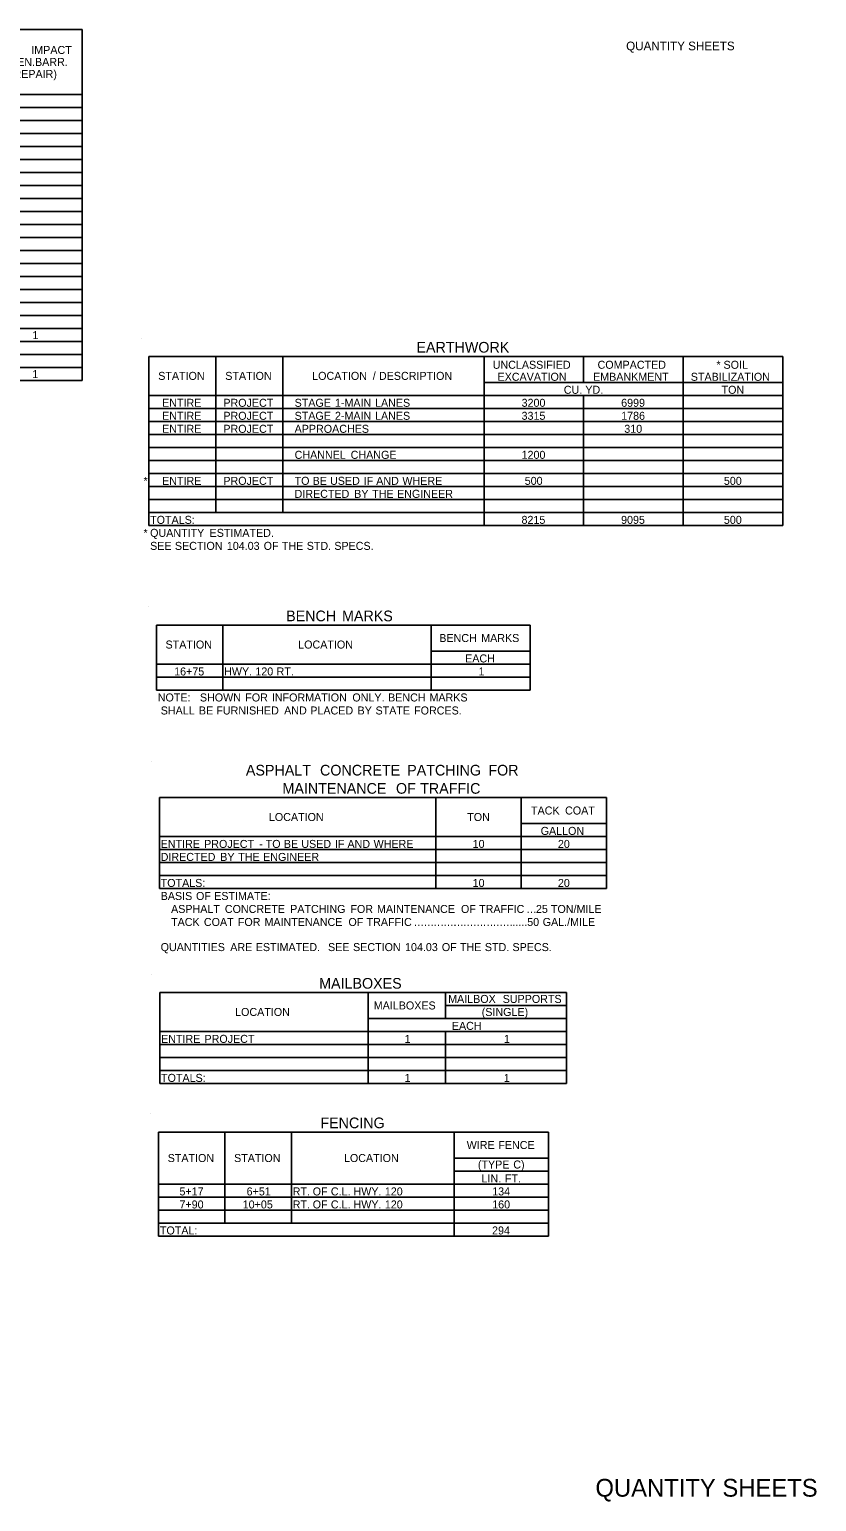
# Model space of a CAD drawing. Extents: x 1940653 to 1945779, y 534266 to 535271.
# Drawn here: x 1941662 to 1942192, y 534266 to 535259 of the extents above; entities that cross this region are included whole.
import ezdxf

# ---------------------------------------------------------------- set-up
doc = ezdxf.new("R2010")
doc.units = 0
for name, color, linetype in [('Default', 7, 'Continuous'), ('R_Border Prem', 7, 'Continuous'), ('R_Logo', 7, 'Continuous')]:
    doc.layers.add(name, color=color, linetype=linetype)

msp = doc.modelspace()

# ---------------------------------------------------------------- linework, layer by layer
at = {"layer": 'Default'}
for p, q in [((1940658.64, 535258.6), (1941697.16, 535258.6)), ((1941697.16, 535021.67), (1941697.16, 535258.6)), ((1941697.16, 535021.67), (1941697.16, 535258.6)), ((1941170.66, 535205.95), (1941697.16, 535205.95)), ((1941222.87, 535214.72), (1941697.16, 535214.72)), ((1941448.83, 535214.72), (1941697.16, 535214.72)), ((1940658.64, 535197.17), (1941697.16, 535197.17)), ((1940658.64, 535188.4), (1941697.16, 535188.4)), ((1940658.64, 535179.62), (1941697.16, 535179.62)), ((1940658.64, 535170.85), (1941697.16, 535170.85)), ((1940658.64, 535162.07), (1941697.16, 535162.07)), ((1940658.64, 535153.3), (1941697.16, 535153.3)), ((1940658.64, 535144.52), (1941697.16, 535144.52)), ((1940658.64, 535135.75), (1941697.16, 535135.75)), ((1940658.64, 535126.97), (1941697.16, 535126.97)), ((1940658.64, 535118.2), (1941697.16, 535118.2)), ((1940658.64, 535109.42), (1941697.16, 535109.42)), ((1940658.64, 535100.65), (1941697.16, 535100.65)), ((1940658.64, 535091.87), (1941697.16, 535091.87)), ((1940658.64, 535083.1), (1941697.16, 535083.1)), ((1940658.64, 535074.32), (1941697.16, 535074.32)), ((1940658.64, 535065.55), (1941697.16, 535065.55)), ((1940658.64, 535056.77), (1941697.16, 535056.77)), ((1940658.64, 535048), (1941697.16, 535048)), ((1940658.64, 535039.22), (1941697.16, 535039.22)), ((1941741.99, 535038.05), (1942169.33, 535038.05)), ((1941741.99, 534923.98), (1941741.99, 535038.05)), ((1941741.99, 534923.98), (1941741.99, 535038.05)), ((1941787.18, 534932.75), (1941787.18, 535038.05)), ((1941832.37, 534932.75), (1941832.37, 535038.05)), ((1941967.95, 534923.98), (1941967.95, 535038.05)), ((1942035.08, 535020.5), (1942035.08, 535038.05)), ((1942102.2, 534923.98), (1942102.2, 535038.05)), ((1942169.33, 534923.98), (1942169.33, 535038.05)), ((1942169.33, 534923.98), (1942169.33, 535038.05)), ((1940658.64, 535030.45), (1941697.16, 535030.45)), ((1940658.64, 535021.67), (1941697.16, 535021.67)), ((1941967.95, 535020.5), (1942169.33, 535020.5)), ((1941741.99, 535011.73), (1942169.33, 535011.73)), ((1941787.18, 534932.75), (1941787.18, 535011.73)), ((1941832.37, 534932.75), (1941832.37, 535011.73)), ((1941967.95, 534932.75), (1941967.95, 535011.73)), ((1942035.08, 534923.98), (1942035.08, 535011.73)), ((1942035.08, 534932.75), (1942035.08, 535011.73)), ((1942102.2, 534932.75), (1942102.2, 535011.73)), ((1941741.99, 535002.95), (1942169.33, 535002.95)), ((1941741.99, 534994.18), (1942169.33, 534994.18)), ((1941741.99, 534985.4), (1942169.33, 534985.4)), ((1941741.99, 534976.63), (1942169.33, 534976.63)), ((1941741.99, 534967.85), (1942169.33, 534967.85)), ((1941741.99, 534959.08), (1942169.33, 534959.08)), ((1941741.99, 534950.3), (1942169.33, 534950.3)), ((1941741.99, 534941.53), (1942169.33, 534941.53)), ((1941741.99, 534932.75), (1941787.18, 534932.75)), ((1941741.99, 534932.75), (1942169.33, 534932.75)), ((1942035.08, 534932.75), (1942102.2, 534932.75)), ((1942102.2, 534932.75), (1942169.33, 534932.75)), ((1941741.99, 534923.98), (1942169.33, 534923.98)), ((1941747.14, 534856.82), (1941998.98, 534856.82)), ((1941747.14, 534812.94), (1941747.14, 534856.82)), ((1941747.14, 534812.94), (1941747.14, 534856.82)), ((1941791.89, 534812.94), (1941791.89, 534856.82)), ((1941932.29, 534812.94), (1941932.29, 534856.82)), ((1941998.98, 534812.94), (1941998.98, 534856.82)), ((1941932.29, 534839.27), (1941998.98, 534839.27)), ((1941998.98, 534812.94), (1941998.98, 534839.27)), ((1941747.14, 534830.49), (1941998.98, 534830.49)), ((1941932.29, 534812.94), (1941932.29, 534830.49)), ((1941747.14, 534821.72), (1941998.98, 534821.72)), ((1941747.14, 534812.94), (1941998.98, 534812.94)), ((1941749.11, 534740.46), (1942050.53, 534740.46)), ((1941749.11, 534679.04), (1941749.11, 534740.46)), ((1941749.11, 534679.04), (1941749.11, 534740.46)), ((1941935.57, 534679.04), (1941935.57, 534740.46)), ((1941993.05, 534679.04), (1941993.05, 534740.46)), ((1942050.53, 534679.04), (1942050.53, 534740.46)), ((1942050.53, 534722.91), (1942050.53, 534740.46)), ((1941993.05, 534722.91), (1942050.53, 534722.91)), ((1941993.05, 534679.04), (1941993.05, 534722.91)), ((1941749.11, 534714.14), (1942050.53, 534714.14)), ((1941935.57, 534679.04), (1941935.57, 534714.14)), ((1942050.53, 534696.59), (1942050.53, 534714.14)), ((1941749.11, 534705.36), (1942050.53, 534705.36)), ((1941749.11, 534696.59), (1942050.53, 534696.59)), ((1941749.11, 534687.81), (1942050.53, 534687.81)), ((1941749.11, 534679.04), (1942050.53, 534679.04)), ((1942050.53, 534679.04), (1942050.53, 534687.81)), ((1941749.37, 534608.95), (1942023.58, 534608.95)), ((1941749.37, 534547.53), (1941749.37, 534608.95)), ((1941749.37, 534547.53), (1941749.37, 534608.95)), ((1941889.77, 534547.53), (1941889.77, 534608.95)), ((1941941.98, 534591.4), (1941941.98, 534608.95)), ((1941941.98, 534600.18), (1942023.58, 534600.18)), ((1942023.58, 534600.18), (1942023.58, 534608.95)), ((1942023.58, 534547.53), (1942023.58, 534608.95)), ((1941889.77, 534591.4), (1942023.58, 534591.4)), ((1941941.98, 534591.4), (1942023.58, 534591.4)), ((1942023.58, 534547.53), (1942023.58, 534591.4)), ((1941749.37, 534582.63), (1942023.58, 534582.63)), ((1941889.77, 534547.53), (1941889.77, 534582.63)), ((1941941.98, 534547.53), (1941941.98, 534582.63)), ((1941941.98, 534547.53), (1941941.98, 534582.63)), ((1941749.37, 534573.85), (1942023.58, 534573.85)), ((1941749.37, 534565.08), (1942023.58, 534565.08)), ((1941749.37, 534556.3), (1942023.58, 534556.3)), ((1941749.37, 534547.53), (1942023.58, 534547.53)), ((1941748.59, 534514.81), (1942011.4, 534514.81)), ((1941748.59, 534444.61), (1941748.59, 534514.81)), ((1941748.59, 534444.61), (1941748.59, 534514.81)), ((1941793.34, 534453.39), (1941793.34, 534514.81)), ((1941838.1, 534453.39), (1941838.1, 534514.81)), ((1941947.78, 534444.61), (1941947.78, 534514.81)), ((1942011.4, 534497.26), (1942011.4, 534514.81)), ((1942011.4, 534444.61), (1942011.4, 534514.81)), ((1941947.78, 534497.26), (1942011.4, 534497.26)), ((1941947.78, 534488.49), (1942011.4, 534488.49)), ((1941947.78, 534488.49), (1942011.4, 534488.49)), ((1942011.4, 534444.61), (1942011.4, 534488.49)), ((1941748.59, 534479.71), (1942011.4, 534479.71)), ((1941748.59, 534470.94), (1942011.4, 534470.94)), ((1941793.34, 534453.39), (1941793.34, 534479.71)), ((1941838.1, 534453.39), (1941838.1, 534479.71)), ((1941947.78, 534444.61), (1941947.78, 534479.71)), ((1941748.59, 534462.16), (1942011.4, 534462.16)), ((1941748.59, 534453.39), (1942011.4, 534453.39)), ((1941748.59, 534444.61), (1942011.4, 534444.61))]:
    msp.add_line(p, q, dxfattribs=at)
at = {"layer": 'R_Logo'}
for p, q in [((1941736.73, 535050.34), (1941736.73, 535050.34)), ((1941741.87, 534869.1), (1941741.87, 534869.1)), ((1941743.84, 534765.03), (1941743.84, 534765.03)), ((1941744.1, 534621.24), (1941744.1, 534621.24)), ((1941743.33, 534527.1), (1941743.33, 534527.1))]:
    msp.add_line(p, q, dxfattribs=at)

# ---------------------------------------------------------------- texts
at = {"layer": 'Default'}
for s, height, p in [(' IMPACT', 5.4, (1941660.75, 535242.06)), ('ATTEN.BARR.', 5.4, (1941639.6, 535233.96)), ('(REPAIR)', 5.4, (1941648.34, 535225.86)), ('1', 5.4, (1941663.51, 535049.68)), ('EARTHWORK', 7.2, (1941922.42, 535040.59)), ('1', 5.4, (1941663.43, 535023.36)), ('STATION', 5.4, (1941748.33, 535022.19)), ('STATION', 5.4, (1941793.52, 535022.19)), ('LOCATION', 5.4, (1941852.13, 535022.19)), (' /', 5.4, (1941890.93, 535022.19)), (' DESCRIPTION', 5.4, (1941895.13, 535022.19)), ('UNCLASSIFIED', 5.4, (1941973.82, 535029.68)), ('EXCAVATION', 5.4, (1941977.08, 535021.58)), ('EMBANKMENT', 5.4, (1942041.47, 535021.58)), ('COMPACTED', 5.4, (1942044.51, 535029.68)), ('STABILIZATION', 5.4, (1942107.36, 535021.58)), ('*', 5.4, (1942124.64, 535029.68)), (' SOIL', 5.4, (1942127.42, 535029.68)), ('CU.', 5.4, (1942021.76, 535012.81)), (' YD.', 5.4, (1942034.24, 535012.81)), ('TON', 5.4, (1942128.11, 535012.81)), ('ENTIRE', 5.4, (1941750.95, 535004.03)), ('PROJECT', 5.4, (1941792.24, 535004.03)), ('STAGE', 5.4, (1941840.27, 535004.03)), (' 1-MAIN', 5.4, (1941865.45, 535004.03)), (' LANES', 5.4, (1941892.49, 535004.03)), ('3200', 5.4, (1941993.3, 535004.03)), ('6999', 5.4, (1942060.42, 535004.03)), ('ENTIRE', 5.4, (1941750.95, 534995.26)), ('PROJECT', 5.4, (1941792.24, 534995.26)), ('STAGE', 5.4, (1941840.27, 534995.26)), (' 2-MAIN', 5.4, (1941865.45, 534995.26)), (' LANES', 5.4, (1941892.49, 534995.26)), ('3315', 5.4, (1941993.27, 534995.26)), ('1786', 5.4, (1942060.42, 534995.26)), ('ENTIRE', 5.4, (1941750.95, 534986.48)), ('PROJECT', 5.4, (1941792.24, 534986.48)), ('APPROACHES', 5.4, (1941840.27, 534986.48)), ('310', 5.4, (1942062.53, 534986.48)), ('CHANNEL', 5.4, (1941840.27, 534968.93)), (' CHANGE', 5.4, (1941876.06, 534968.93)), ('1200', 5.4, (1941993.3, 534968.93)), ('*', 5.4, (1941738.44, 534951.38)), ('ENTIRE', 5.4, (1941750.95, 534951.38)), ('PROJECT', 5.4, (1941792.24, 534951.38)), ('TO', 5.4, (1941840.27, 534951.38)), ('DIRECTED', 5.4, (1941840.27, 534942.61)), (' BE', 5.4, (1941850.41, 534951.38)), (' USED', 5.4, (1941862.17, 534951.38)), (' BY', 5.4, (1941878.44, 534942.61)), (' IF', 5.4, (1941884.83, 534951.38)), (' THE', 5.4, (1941890.54, 534942.61)), (' AND', 5.4, (1941893.28, 534951.38)), (' ENGINEER', 5.4, (1941907.33, 534942.61)), (' WHERE', 5.4, (1941910.91, 534951.38)), ('500', 5.4, (1941995.4, 534951.38)), ('500', 5.4, (1942129.66, 534951.38)), ('TOTALS:', 5.4, (1941742.87, 534925.06)), ('8215', 5.4, (1941993.24, 534925.06)), ('9095', 5.4, (1942060.37, 534925.06)), ('500', 5.4, (1942129.66, 534925.06)), ('*', 5.4, (1941738.44, 534916.28)), ('QUANTITY', 5.4, (1941742.87, 534916.28)), (' ESTIMATED.', 5.4, (1941780.96, 534916.28)), ('SEE', 5.4, (1941742.87, 534907.51)), (' SECTION', 5.4, (1941757.57, 534907.51)), (' 104.03', 5.4, (1941792.58, 534907.51)), (' OF', 5.4, (1941817.4, 534907.51)), (' THE', 5.4, (1941829.63, 534907.51)), (' STD.', 5.4, (1941846.42, 534907.51)), (' SPECS.', 5.4, (1941865.04, 534907.51)), ('BENCH', 7.2, (1941834.56, 534859.36)), (' MARKS', 7.2, (1941869.57, 534859.36)), ('BENCH', 5.4, (1941937.81, 534845.34)), (' MARKS', 5.4, (1941964.06, 534845.34)), ('STATION', 5.4, (1941753.26, 534840.95)), ('LOCATION', 5.4, (1941842.69, 534840.95)), ('16+75', 5.4, (1941759.07, 534822.8)), ('HWY.', 5.4, (1941792.77, 534822.8)), (' 120', 5.4, (1941811.81, 534822.8)), (' RT.', 5.4, (1941826.12, 534822.8)), ('EACH', 5.4, (1941955.23, 534831.57)), ('1', 5.4, (1941964.23, 534822.8)), ('NOTE:', 5.4, (1941748.01, 534805.25)), ('   SHOWN', 5.4, (1941770.41, 534805.25)), (' FOR', 5.4, (1941805, 534805.25)), (' INFORMATION', 5.4, (1941822.92, 534805.25)), (' ONLY.', 5.4, (1941877.21, 534805.25)), (' BENCH', 5.4, (1941901.29, 534805.25)), (' MARKS', 5.4, (1941929.19, 534805.25)), (' SHALL', 5.4, (1941748.01, 534796.47)), (' BE', 5.4, (1941773.74, 534796.47)), (' FURNISHED', 5.4, (1941785.5, 534796.47)), (' AND', 5.4, (1941831.21, 534796.47)), (' PLACED', 5.4, (1941848.84, 534796.47)), (' BY', 5.4, (1941880.72, 534796.47)), (' STATE', 5.4, (1941892.83, 534796.47)), (' FORCES.', 5.4, (1941918.84, 534796.47)), ('ASPHALT', 7.2, (1941807.44, 534755.29)), (' CONCRETE', 7.2, (1941854.74, 534755.29)), (' PATCHING', 7.2, (1941913.49, 534755.29)), (' FOR', 7.2, (1941968.22, 534755.29)), ('MAINTENANCE', 7.2, (1941832.09, 534743)), (' OF', 7.2, (1941905.93, 534743)), (' TRAFFIC', 7.2, (1941922.23, 534743)), ('LOCATION', 5.4, (1941822.94, 534724.6)), ('TON', 5.4, (1941956.65, 534724.6)), ('TACK', 5.4, (1941999.66, 534728.99)), (' COAT', 5.4, (1942020.6, 534728.99)), ('GALLON', 5.4, (1942006.16, 534715.22)), ('ENTIRE', 5.4, (1941749.98, 534706.44)), (' PROJECT', 5.4, (1941777.25, 534706.44)), (' -', 5.4, (1941814.41, 534706.44)), (' TO', 5.4, (1941818.78, 534706.44)), (' BE', 5.4, (1941831.02, 534706.44)), (' USED', 5.4, (1941842.78, 534706.44)), (' IF', 5.4, (1941865.44, 534706.44)), (' AND', 5.4, (1941873.89, 534706.44)), (' WHERE', 5.4, (1941891.52, 534706.44)), ('10', 5.4, (1941960.3, 534706.44)), ('20', 5.4, (1942017.78, 534706.44)), ('DIRECTED', 5.4, (1941749.98, 534697.67)), (' BY', 5.4, (1941788.15, 534697.67)), (' THE', 5.4, (1941800.25, 534697.67)), (' ENGINEER', 5.4, (1941817.04, 534697.67)), ('TOTALS:', 5.4, (1941749.98, 534680.12)), ('10', 5.4, (1941960.3, 534680.12)), ('20', 5.4, (1942017.78, 534680.12)), ('BASIS', 5.4, (1941749.98, 534671.34)), (' OF', 5.4, (1941771.82, 534671.34)), (' ESTIMATE:', 5.4, (1941784.05, 534671.34)), ('ASPHALT', 5.4, (1941757, 534662.57)), ('TACK', 5.4, (1941757, 534653.79)), (' COAT', 5.4, (1941777.11, 534653.79)), (' CONCRETE', 5.4, (1941791.24, 534662.57)), (' FOR', 5.4, (1941800.02, 534653.79)), (' MAINTENANCE', 5.4, (1941817.94, 534653.79)), (' PATCHING', 5.4, (1941835.27, 534662.57)), (' OF', 5.4, (1941874.55, 534653.79)), (' FOR', 5.4, (1941875.89, 534662.57)), (' TRAFFIC', 5.4, (1941886.78, 534653.79)), (' MAINTENANCE', 5.4, (1941893.81, 534662.57)), (' OF', 5.4, (1941950.42, 534662.57)), (' TRAFFIC', 5.4, (1941962.65, 534662.57)), ('.....50', 5.4, (1941987.03, 534653.79)), ('…', 5.4, (1941996.3, 534662.57)), ('25', 5.4, (1942002.96, 534662.57)), (' GAL./MILE', 5.4, (1942005.53, 534653.79)), (' TON/MILE', 5.4, (1942011.05, 534662.57)), ('…', 5.4, (1941920.43, 534653.79)), ('…', 5.4, (1941927.09, 534653.79)), ('…', 5.4, (1941933.75, 534653.79)), ('…', 5.4, (1941940.41, 534653.79)), ('…', 5.4, (1941947.07, 534653.79)), ('…', 5.4, (1941953.73, 534653.79)), ('…', 5.4, (1941960.39, 534653.79)), ('…', 5.4, (1941967.05, 534653.79)), ('…', 5.4, (1941973.71, 534653.79)), ('…', 5.4, (1941980.37, 534653.79)), ('QUANTITIES', 5.4, (1941749.98, 534636.85)), (' ARE', 5.4, (1941794.87, 534636.85)), (' ESTIMATED.', 5.4, (1941812.08, 534636.85)), ('  SEE', 5.4, (1941858.79, 534636.85)), (' SECTION', 5.4, (1941877.68, 534636.85)), (' 104.03', 5.4, (1941912.7, 534636.85)), (' OF', 5.4, (1941937.51, 534636.85)), (' THE', 5.4, (1941949.74, 534636.85)), (' STD.', 5.4, (1941966.53, 534636.85)), (' SPECS.', 5.4, (1941985.15, 534636.85)), ('MAILBOXES', 7.2, (1941856.82, 534611.5)), ('MAILBOXES', 5.4, (1941893.63, 534597.48)), ('MAILBOX', 5.4, (1941943.77, 534601.87)), (' SUPPORTS', 5.4, (1941978.55, 534601.87)), ('LOCATION', 5.4, (1941800.17, 534593.09)), ('(SINGLE)', 5.4, (1941966.42, 534593.09)), ('ENTIRE', 5.4, (1941750.24, 534574.93)), (' PROJECT', 5.4, (1941777.51, 534574.93)), ('1', 5.4, (1941914.47, 534574.93)), ('EACH', 5.4, (1941946.27, 534583.71)), ('1', 5.4, (1941981.38, 534574.93)), ('TOTALS:', 5.4, (1941750.24, 534548.61)), ('1', 5.4, (1941914.39, 534548.61)), ('1', 5.4, (1941981.3, 534548.61)), ('FENCING', 7.2, (1941857.66, 534517.36)), ('WIRE', 5.4, (1941956.28, 534503.34)), (' FENCE', 5.4, (1941975.61, 534503.34)), ('STATION', 5.4, (1941754.71, 534494.56)), ('STATION', 5.4, (1941799.46, 534494.56)), ('LOCATION', 5.4, (1941873.54, 534494.56)), ('(TYPE', 5.4, (1941963.84, 534490.18)), (' C)', 5.4, (1941985.68, 534490.18)), ('LIN.', 5.4, (1941966.28, 534480.79)), (' FT.', 5.4, (1941980.01, 534480.79)), ('5+17', 5.4, (1941762.64, 534472.02)), ('6+51', 5.4, (1941807.92, 534472.02)), ('RT.', 5.4, (1941838.97, 534472.02)), (' OF', 5.4, (1941850.47, 534472.02)), (' C.L.', 5.4, (1941862.7, 534472.02)), (' HWY.', 5.4, (1941877.97, 534472.02)), (' 120', 5.4, (1941899.1, 534472.02)), ('134', 5.4, (1941973.48, 534472.02)), ('7+90', 5.4, (1941762.65, 534463.24)), ('10+05', 5.4, (1941805.28, 534463.24)), ('RT.', 5.4, (1941838.97, 534463.24)), (' OF', 5.4, (1941850.47, 534463.24)), (' C.L.', 5.4, (1941862.7, 534463.24)), (' HWY.', 5.4, (1941877.97, 534463.24)), (' 120', 5.4, (1941899.1, 534463.24)), ('160', 5.4, (1941973.48, 534463.24)), ('TOTAL:', 5.4, (1941749.47, 534445.69)), ('294', 5.4, (1941973.39, 534445.69))]:
    msp.add_text(s, height=height, dxfattribs=at).set_placement(p)
at = {"layer": 'R_Border Prem'}
msp.add_text('QUANTITY SHEETS', height=5.862, dxfattribs=at).set_placement((1942063.77, 535244.53))
at = {"layer": 'R_Logo'}
msp.add_text('QUANTITY SHEETS', height=12, dxfattribs=at).set_placement((1942043.08, 534268.8))

doc.saveas('drawing.dxf')
